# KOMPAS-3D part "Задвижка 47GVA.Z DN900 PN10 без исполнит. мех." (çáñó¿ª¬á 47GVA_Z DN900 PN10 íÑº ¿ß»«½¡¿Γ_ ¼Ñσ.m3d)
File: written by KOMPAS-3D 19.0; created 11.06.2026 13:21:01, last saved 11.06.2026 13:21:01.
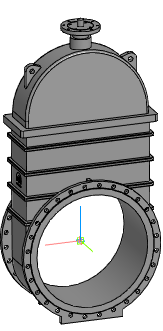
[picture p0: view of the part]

Document properties: Автор: Евгений; Полное имя файла: Z:\3.Личные\kachalov\001_3d для проектировщиков\2.2 Тип 47GVA, 47GVA.Z\_stp\_stp_Задвижка 47GVA.Z DN350-DN1200 без исп.мех\Задвижка 47GVA_Z DN900 PN10 без исполнит_ мех.m3d

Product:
- Part/product: Задвижка 47GVA.Z DN900 PN10 без исполнит. мех.

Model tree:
1. Операция без истории:1  (labels: Задвижка 47GVA.Z DN900 PN10 без исполнит. мех.)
